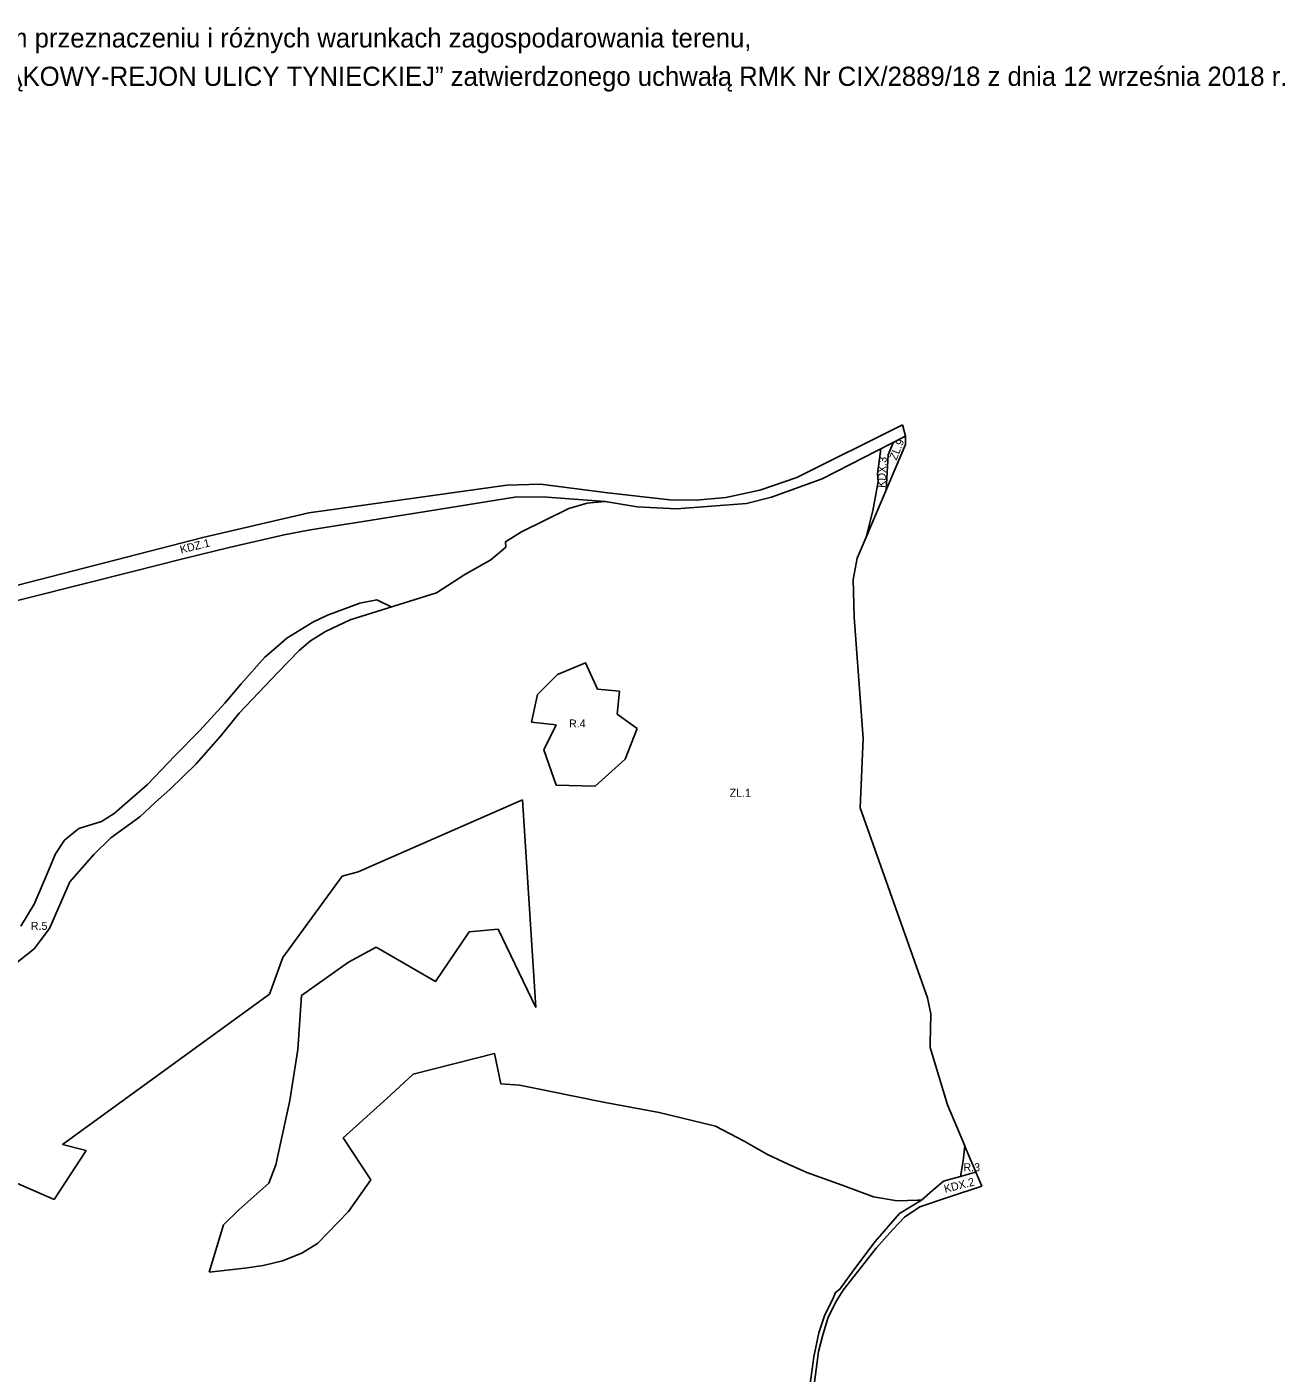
# Model space of a CAD drawing. Extents: x 7418237 to 7420198, y 5543414 to 5545133.
# Drawn here: x 7419412 to 7420198, y 5544292 to 5545133 of the extents above; entities that cross this region are included whole.
import ezdxf

# ---------------------------------------------------------------- set-up
doc = ezdxf.new("R2010")
doc.units = 0
for name, color, linetype in [('info', 7, 'Continuous'), ('linie rozgraniczające', 7, 'Continuous'), ('przeznaczenia terenów', 7, 'Continuous')]:
    doc.layers.add(name, color=color, linetype=linetype)

msp = doc.modelspace()

# ---------------------------------------------------------------- linework, layer by layer
at = {"layer": 'linie rozgraniczające'}
for p, q in [((7419960.63, 5544877.11), (7419958.6, 5544884.24)), ((7419960.63, 5544877.11), (7419908.55, 5544850.56)), ((7419960.67, 5544872.05), (7419960.63, 5544877.11)), ((7419960.63, 5544877.11), (7419960.63, 5544877.11)), ((7419935.92, 5544814.01), (7419960.67, 5544872.05)), ((7419943.12, 5544853.73), (7419945.24, 5544869.26)), ((7419908.55, 5544850.56), (7419876.91, 5544838.99)), ((7419943.59, 5544848.92), (7419943.12, 5544853.73)), ((7419940.19, 5544830.48), (7419943.59, 5544848.92)), ((7419772.96, 5544836.35), (7419736.68, 5544839.05)), ((7419817.57, 5544831.7), (7419793.04, 5544832.94)), ((7419861.15, 5544835.11), (7419817.57, 5544831.7)), ((7419876.91, 5544838.99), (7419861.15, 5544835.11)), ((7419935.92, 5544814.01), (7419940.19, 5544830.48)), ((7419710.97, 5544807.74), (7419710.97, 5544807.74)), ((7419710.97, 5544807.74), (7419710.97, 5544807.74)), ((7419930.35, 5544800.94), (7419935.92, 5544814.01)), ((7419927.89, 5544787.52), (7419930.35, 5544800.94)), ((7419928.52, 5544763.99), (7419927.89, 5544787.52)), ((7419934.11, 5544688.3), (7419928.52, 5544763.99)), ((7419588.96, 5544749.23), (7419581.69, 5544743.26)), ((7419598.28, 5544755.03), (7419588.96, 5544749.23)), ((7419581.69, 5544743.26), (7419568.63, 5544729.65)), ((7419568.63, 5544729.65), (7419544.35, 5544704.04)), ((7419730.67, 5544715.69), (7419743.21, 5544728.31)), ((7419726.98, 5544698.38), (7419730.67, 5544715.69)), ((7419768.06, 5544719.15), (7419781.83, 5544717.76)), ((7419544.35, 5544704.04), (7419532.77, 5544689.94)), ((7419742.33, 5544696.82), (7419726.98, 5544698.38)), ((7419734.66, 5544681.1), (7419742.33, 5544696.82)), ((7419793.02, 5544694.47), (7419785.34, 5544675.36)), ((7419932.21, 5544645), (7419934.11, 5544688.3)), ((7419742.25, 5544659.16), (7419734.66, 5544681.1)), ((7419785.34, 5544675.36), (7419766.79, 5544658.4)), ((7419766.79, 5544658.4), (7419742.25, 5544659.16)), ((7419721.25, 5544649.97), (7419729.7, 5544520.1)), ((7419974.22, 5544526.17), (7419932.21, 5544645)), ((7419453.5, 5544615.77), (7419438.52, 5544598.59)), ((7419438.52, 5544598.59), (7419425.89, 5544569.53)), ((7419706.04, 5544569.2), (7419687.89, 5544567.52)), ((7419729.7, 5544520.1), (7419706.04, 5544569.2)), ((7419976.37, 5544516.12), (7419974.22, 5544526.17)), ((7419729.7, 5544520.1), (7419729.7, 5544520.1)), ((7419976, 5544497.79), (7419976.37, 5544516.12)), ((7419975.95, 5544495.24), (7419976, 5544497.79)), ((7419986.78, 5544459.37), (7419975.95, 5544495.24)), ((7419707.87, 5544472.37), (7419719.48, 5544471.54)), ((7419575.95, 5544462.13), (7419567.27, 5544421.94)), ((7419997.58, 5544433.72), (7419986.78, 5544459.37)), ((7419996.66, 5544424.27), (7419997.58, 5544433.72)), ((7420008.22, 5544408.46), (7419997.5, 5544433.92)), ((7419994.99, 5544414.56), (7419996.66, 5544424.27)), ((7419984.22, 5544411.66), (7419989.61, 5544413.11)), ((7419989.61, 5544413.11), (7419994.99, 5544414.56)), ((7419970.61, 5544399.87), (7419977.42, 5544405.76)), ((7419977.42, 5544405.76), (7419984.22, 5544411.66)), ((7419968.36, 5544399.8), (7419970.61, 5544399.87)), ((7419583.51, 5544366.58), (7419593.34, 5544372.76)), ((7419525.6, 5544354.8), (7419547.84, 5544357.24))]:
    msp.add_line(p, q, dxfattribs=at)
for points in [[(7419958.6, 5544884.24), (7419892.68, 5544851.31), (7419869.66, 5544843.42), (7419848.36, 5544838.88), (7419829.87, 5544837.07), (7419813.25, 5544837.28), (7419774.71, 5544841.72), (7419732.52, 5544847.12), (7419711.42, 5544846.64), (7419587.86, 5544829.18), (7419521.6, 5544813.9), (7419331.58, 5544764.86)], [(7419952.76, 5544873.1), (7419949.65, 5544865.59), (7419948.51, 5544843.54)], [(7419736.68, 5544839.05), (7419717.87, 5544839.31), (7419655.8, 5544829.33), (7419641.23, 5544826.99), (7419625.73, 5544824.5)], [(7419765.97, 5544835.64), (7419761.8, 5544835.25), (7419750.3, 5544832), (7419735.46, 5544824.66)], [(7419793.04, 5544832.94), (7419772.96, 5544836.35), (7419768.62, 5544835.92), (7419765.97, 5544835.64)], [(7418875.3, 5544643.75), (7418890.85, 5544650.93), (7418903.28, 5544655.5), (7418930.37, 5544662.82), (7418949.48, 5544666.88), (7419051.76, 5544689.48), (7419173.91, 5544717.09), (7419210.82, 5544725.79), (7419252.57, 5544735.92), (7419477.85, 5544792.51), (7419492.73, 5544796.3), (7419508.24, 5544800.25), (7419537.97, 5544807.59), (7419572.41, 5544815.47), (7419587.6, 5544818.37), (7419604.4, 5544821.07), (7419625.73, 5544824.5)], [(7419735.46, 5544824.66), (7419720.61, 5544817.32), (7419710.74, 5544811.15), (7419710.97, 5544807.74)], [(7419710.97, 5544807.74), (7419701.44, 5544799.91), (7419685.36, 5544790.65), (7419667.67, 5544779.22), (7419613.71, 5544762.48), (7419598.28, 5544755.03)], [(7419408, 5544571.06), (7419416.32, 5544584.74), (7419423.1, 5544600.85), (7419429.47, 5544616.17), (7419435.26, 5544624.75), (7419443.05, 5544631.13), (7419444.2, 5544632.06), (7419458.22, 5544636.46), (7419466.3, 5544641.4), (7419487.05, 5544659.52), (7419504.21, 5544677.34), (7419519.73, 5544693.21), (7419535.28, 5544710.27), (7419545.54, 5544722.31), (7419560.29, 5544739), (7419567.47, 5544745.21), (7419574.11, 5544750.95), (7419590.27, 5544760.85), (7419599.53, 5544765.36), (7419619.59, 5544772.77), (7419630.37, 5544774.87), (7419639.33, 5544770.43)], [(7419743.21, 5544728.31), (7419760.69, 5544735.63), (7419768.06, 5544719.15)], [(7419781.83, 5544717.76), (7419780.48, 5544703.55), (7419793.02, 5544694.47)], [(7419532.77, 5544689.94), (7419517.38, 5544672.47), (7419501.09, 5544656.32)], [(7419501.09, 5544656.32), (7419492.01, 5544648.46), (7419482.18, 5544639.37), (7419464.12, 5544626.17), (7419453.5, 5544615.77)], [(7419608.56, 5544602.21), (7419618.65, 5544605.04), (7419721.25, 5544649.97)], [(7419563.28, 5544528.57), (7419571.57, 5544551.44), (7419608.56, 5544602.21)], [(7419425.89, 5544569.53), (7419416.27, 5544556.88), (7419342.19, 5544498.38), (7419339.34, 5544494.61), (7419339.28, 5544487.93)], [(7419687.89, 5544567.52), (7419666.88, 5544536.37), (7419629.87, 5544557.92)], [(7419629.87, 5544557.92), (7419612.58, 5544548.55), (7419583.25, 5544527.61)], [(7419428.77, 5544400.2), (7419448.69, 5544430.73), (7419434.01, 5544434.51), (7419563.28, 5544528.57)], [(7419583.25, 5544527.61), (7419581.03, 5544493.9), (7419575.95, 5544462.13)], [(7419729.7, 5544520.1), (7419729.7, 5544520.1)], [(7419636.6, 5544463.2), (7419652.96, 5544478.57), (7419703.8, 5544491.42), (7419707.87, 5544472.37)], [(7419719.48, 5544471.54), (7419733.04, 5544468.83)], [(7419626.65, 5544412.38), (7419609.28, 5544438.82), (7419636.6, 5544463.2)], [(7419733.04, 5544468.83), (7419751.21, 5544465.17), (7419772.88, 5544460.82), (7419806.61, 5544454.6), (7419841.81, 5544445.92)], [(7419841.81, 5544445.92), (7419859.86, 5544436.6), (7419874.45, 5544428.22), (7419887.21, 5544422.23)], [(7419567.27, 5544421.94), (7419562.92, 5544410.36), (7419544.13, 5544393.79), (7419534.54, 5544384.27), (7419525.6, 5544354.8)], [(7419887.21, 5544422.23), (7419898.99, 5544416.97), (7419921.07, 5544409.06)], [(7419398.82, 5544415.27), (7419397.81, 5544413.7), (7419428.77, 5544400.2)], [(7419593.34, 5544372.76), (7419612.68, 5544392.64), (7419626.65, 5544412.38)], [(7420004.49, 5544417.32), (7420001.94, 5544416.58), (7419994.99, 5544414.56)], [(7419796.88, 5544024.41), (7419880.5, 5544177.97), (7419890.57, 5544194.91), (7419893.75, 5544204.23), (7419895.58, 5544212.12), (7419897.77, 5544231.17), (7419902.12, 5544273.29), (7419905.34, 5544298.82), (7419906.29, 5544305.28), (7419908.63, 5544314.85), (7419912.35, 5544326.62), (7419917.38, 5544336.85), (7419921.73, 5544343.62), (7419942.3, 5544369.78), (7419952.58, 5544381.37), (7419959.87, 5544389.22), (7419969.6, 5544395.68), (7419987.34, 5544401.57), (7420008.22, 5544408.46)], [(7419921.07, 5544409.06), (7419940.62, 5544401.86), (7419955.45, 5544399.39), (7419968.36, 5544399.8)], [(7419876.63, 5544176.05), (7419883.58, 5544188.94), (7419888.77, 5544197.49), (7419892.78, 5544211.37), (7419894.69, 5544226.34), (7419898.17, 5544262.21), (7419898.33, 5544263.46), (7419900.88, 5544283.58), (7419903.27, 5544301.85), (7419906.46, 5544316.97), (7419910.22, 5544328.04), (7419914.99, 5544337.49), (7419916.87, 5544342.11), (7419919.47, 5544344.16), (7419928.84, 5544357.02), (7419941.68, 5544373.89), (7419956.87, 5544391.47), (7419970.61, 5544399.87)], [(7419547.84, 5544357.24), (7419559.21, 5544358.93), (7419571.28, 5544361.79), (7419583.51, 5544366.58)]]:
    msp.add_lwpolyline(points, dxfattribs=at)

# ---------------------------------------------------------------- texts
at = {"layer": 'info'}
for s, p in [('Materiał pomocniczy zawierający linie rozgraniczające teren o różnym przeznaczeniu i różnych warunkach zagospodarowania terenu, ', (7418916.21, 5545120.04)), ('opracowane w skali 1:1000 pochodzące z Miejscowego Planu Zagospodarowania Przestrzennego obszaru „OBSZAR ŁĄKOWY-REJON ULICY TYNIECKIEJ” zatwierdzonego uchwałą RMK Nr CIX/2889/18 z dnia 12 września 2018 r.', (7418550.01, 5545096.04))]:
    msp.add_text(s, height=12, dxfattribs=at).set_placement(p)
at = {"layer": 'przeznaczenia terenów'}
for s, rotation, p in [('ZL.9', 67.75957, (7419954.86, 5544861.76)), ('KDX.3', 87.23714, (7419947.96, 5544844.83)), ('KDZ.1', 14.13548, (7419508.05, 5544803.74)), ('KDX.2', 14.13548, (7419985.32, 5544404.32))]:
    msp.add_text(s, height=5, rotation=rotation, dxfattribs=at).set_placement(p)
for s, p in [('R.4', (7419750.36, 5544695.13)), ('ZL.1', (7419850.69, 5544651.81)), ('R.5', (7419414.13, 5544568.69)), ('R.3', (7419996.73, 5544417.86))]:
    msp.add_text(s, height=5, dxfattribs=at).set_placement(p)

doc.saveas('drawing.dxf')
